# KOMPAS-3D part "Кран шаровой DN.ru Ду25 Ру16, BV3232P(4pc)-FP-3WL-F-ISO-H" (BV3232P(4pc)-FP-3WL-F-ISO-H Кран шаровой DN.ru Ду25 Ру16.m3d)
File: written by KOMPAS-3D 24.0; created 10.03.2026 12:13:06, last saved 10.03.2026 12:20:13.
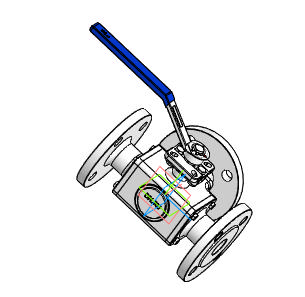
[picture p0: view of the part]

Document properties: Автор: R2D2; Полное имя файла: BV3232P(4pc)-FP-3WL-F-ISO-H Кран шаровой DN.ru Ду25 Ру16.cdw

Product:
- Part/product: Кран шаровой DN.ru Ду25 Ру16  | designation BV3232P(4pc)-FP-3WL-F-ISO-H
    Масса: 5.6
    Раздел спецификации: Прочие изделия
    Форматы листов документа: A2
    Примечание: D160-36357

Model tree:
1. Операция без истории:2

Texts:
  BV3232P(4pc)-FP-3WL-F-ISO-H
